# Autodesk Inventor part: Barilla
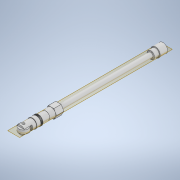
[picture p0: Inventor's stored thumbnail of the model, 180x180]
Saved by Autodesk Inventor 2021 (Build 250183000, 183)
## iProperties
Created: 2021-02
Part Number: Barilla
Material: Genérico
Document SubType Name: Modeling
Designer: ATOUZA
Density: 1 g/cm^3
Appearance: Valor por defecto
Author: ATOUZA
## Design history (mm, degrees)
sketch "Boceto1"
  geometry: C1 r 2.5 at (0, 0); 1 further point
  constraints: 1 centre point, 1 coincident
  dimensions: "d0" = 5 diameter of C1
extrude "Extrusión1" new body sketch "Boceto1" distance "d1" = 98; taper "d2" = 0 deg
sketch "Boceto2"
  geometry: C1 r 4 at (0, 0); 1 further point
  constraints: 1 centre point, 1 coincident
  dimensions: "d3" = 8 diameter of C1
extrude "Extrusión2" join sketch "Boceto2" distance "d4" = 5; taper "d5" = 0 deg
sketch "Boceto3"
  geometry: C1 r 5 at (0, 0); 1 further point
  constraints: 1 centre point, 1 coincident
  dimensions: "d6" = 10 diameter of C1
extrude "Extrusión3" join sketch "Boceto3" distance "d7" = 8; taper "d8" = 0 deg
sketch "Boceto4"
  geometry: L1 (-2.887, -5)-(-5.774, 0); L2 (-5.774, 0)-(-2.887, 5); L3 (-2.887, 5)-(2.887, 5); L4 (2.887, 5)-(5.774, 0); L5 (5.774, 0)-(2.887, -5); L6 (2.887, -5)-(-2.887, -5); L7 (5, 0)-(-4.981, 0); 3 further points
  constraints: 14 end point, 1 coincident, 1 horizontal, 1 horizontal alignment, 1 parallel, 14 other
  dimensions: "d9" = 10 distance between parallel lines of L3 L6
extrude "Extrusión4" join sketch "Boceto4" distance "d10" = 7.8; taper "d11" = 0 deg
node "Plano de trabajo1"
sketch "Boceto5"
  geometry: C1 r 5 at (0, 0); 2 further points
  constraints: 1 centre point, 1 coincident
sketch "Boceto6"
  geometry: C1 r 4 at (0, 0); 1 further point
  constraints: 1 centre point, 1 coincident
  dimensions: "d13" = 8 diameter of C1
feature "Solevación1" sketch "Boceto5", "Boceto6" dims "d14" = 0, "d15" = 90 deg, "d16" = 0, "d17" = 90 deg
sketch "Boceto13"
  geometry: C1 r 4 at (0, 0); 1 further point
  constraints: 1 centre point, 1 coincident
  dimensions: "d45" = 8 diameter of C1
extrude "Extrusión11" new body sketch "Boceto13" distance "d46" = 8; taper "d47" = 0 deg
sketch "Boceto7"
  geometry: L1 (-0.25, -5)-(-0.25, -4.711); L2 (-0.25, -4.711)-(0.25, -4.711); L3 (0.25, -4.711)-(0.25, -5); L4 (-2.887, -5)-(2.887, -5) reference; L5 (0.25, -5.289)-(-0.25, -4.711); L6 (-0.25, -5.289)-(0.25, -4.711); L7 (0.984, -4.613)-(1.029, -4.899); L8 (0.49, -4.692)-(0.984, -4.613); L9 (0.535, -4.978)-(0.49, -4.692); L10 (1.693, -4.403)-(1.783, -4.678); L11 (1.218, -4.557)-(1.693, -4.403); L12 (1.307, -4.833)-(1.218, -4.557); L13 (2.361, -4.084)-(2.493, -4.342); L14 (1.916, -4.311)-(2.361, -4.084); L15 (2.047, -4.569)-(1.916, -4.311); L16 (2.971, -3.664)-(3.141, -3.898); L17 (2.567, -3.958)-(2.971, -3.664); L18 (2.737, -4.192)-(2.567, -3.958); L19 (3.508, -3.154)-(3.712, -3.359); L20 (3.154, -3.508)-(3.508, -3.154); L21 (3.359, -3.712)-(3.154, -3.508); L22 (3.958, -2.567)-(4.192, -2.737); L23 (3.664, -2.971)-(3.958, -2.567); L24 (3.898, -3.141)-(3.664, -2.971); L25 (4.311, -1.916)-(4.569, -2.047); L26 (4.084, -2.361)-(4.311, -1.916); L27 (4.342, -2.493)-(4.084, -2.361); L28 (4.557, -1.218)-(4.833, -1.307); L29 (4.403, -1.693)-(4.557, -1.218); L30 (4.678, -1.783)-(4.403, -1.693); L31 (4.692, -0.49)-(4.978, -0.535); L32 (4.613, -0.984)-(4.692, -0.49); L33 (4.899, -1.029)-(4.613, -0.984); L34 (4.711, 0.25)-(5, 0.25); L35 (4.711, -0.25)-(4.711, 0.25); L36 (5, -0.25)-(4.711, -0.25); L37 (4.613, 0.984)-(4.899, 1.029); L38 (4.692, 0.49)-(4.613, 0.984); L39 (4.978, 0.535)-(4.692, 0.49); L40 (4.403, 1.693)-(4.678, 1.783); L41 (4.557, 1.218)-(4.403, 1.693); L42 (4.833, 1.307)-(4.557, 1.218); L43 (4.084, 2.361)-(4.342, 2.493); L44 (4.311, 1.916)-(4.084, 2.361); L45 (4.569, 2.047)-(4.311, 1.916); L46 (3.664, 2.971)-(3.898, 3.141); L47 (3.958, 2.567)-(3.664, 2.971); L48 (4.192, 2.737)-(3.958, 2.567); L49 (3.154, 3.508)-(3.359, 3.712); L50 (3.508, 3.154)-(3.154, 3.508); L51 (3.712, 3.359)-(3.508, 3.154); L52 (2.567, 3.958)-(2.737, 4.192); L53 (2.971, 3.664)-(2.567, 3.958); L54 (3.141, 3.898)-(2.971, 3.664); L55 (1.916, 4.311)-(2.047, 4.569); L56 (2.361, 4.084)-(1.916, 4.311); L57 (2.493, 4.342)-(2.361, 4.084); L58 (1.218, 4.557)-(1.307, 4.833); L59 (1.693, 4.403)-(1.218, 4.557); L60 (1.783, 4.678)-(1.693, 4.403); L61 (0.49, 4.692)-(0.535, 4.978); L62 (0.984, 4.613)-(0.49, 4.692); L63 (1.029, 4.899)-(0.984, 4.613); L64 (-0.25, 4.711)-(-0.25, 5)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; 83 further points
  constraints: 244 end point, 81 point on line, 3 midpoint, 1 parallel, 402 other
  dimensions: "d20" = 0.5 distance of L1.end L2.end; "d23" = 360 deg dimension on point (0, 0) L2.end (derived)
extrude "Extrusión5" new body sketch "Boceto7" distance "d25" = 2.3; taper "d26" = 0 deg
sketch "Boceto8"
  geometry: C1 r 5 at (0, 0); 1 further point
  constraints: 1 centre point, 1 coincident
  dimensions: "d27" = 10 diameter of C1
extrude "Extrusión6" join sketch "Boceto8" distance "d28" = 4.2; taper "d29" = 0 deg
sketch "Boceto9"
  geometry: C1 r 4.5 at (0, 0); 1 further point
  constraints: 1 centre point, 1 coincident
  dimensions: "d30" = 9 diameter of C1
extrude "Extrusión7" join sketch "Boceto9" distance "d31" = 4.2; taper "d32" = 0 deg
sketch "Boceto10"
  geometry: L1 (3.742, 2.5)-(-3.742, 2.5); L2 (-3.742, -2.5)-(3.742, -2.5); L3 (3.742, 2.5)-(-3.742, -2.5); L4 (-3.742, 2.5)-(3.742, -2.5); A1 r 4.5 centre (0, 0) between (-3.742, -2.5) and (3.742, -2.5); A2 r 4.5 centre (0, 0) between (3.742, 2.5) and (-3.742, 2.5); 2 further points
  constraints: 8 end point, 4 point on circle, 2 centre point, 2 coincident, 2 midpoint, 1 horizontal, 1 parallel
extrude "Extrusión8" join sketch "Boceto10" distance "d34" = 8.2; taper "d35" = 0 deg
sketch "Boceto11"
  geometry: L1 (0, -8.2)-(7.483, -8.2) reference; C1 r 1.25 at (3.742, -5.2); 1 further point
  constraints: 1 centre point
  dimensions: "d36" = 2.5 diameter of C1; "d37" = 3 distance from line of C1.centre L1
extrude "Extrusión9" cut sketch "Boceto11" distance "d38" = 8.2; taper "d40" = 0 deg; dims "d39" = 4.1, "d41" = 0
node "Plano de trabajo2"
sketch "Boceto12"
  geometry: C1 r 5 at (3.742, -5.078); 1 further point
  constraints: 1 centre point
  dimensions: "d42" = 10 diameter of C1
extrude "Extrusión10" join sketch "Boceto12" stored distance "d43" = 4; taper "d44" = 0 deg
node "Sólido1"
node "Sólido2"
node "Sólido3"
other parameters: "d12" = 5.5
